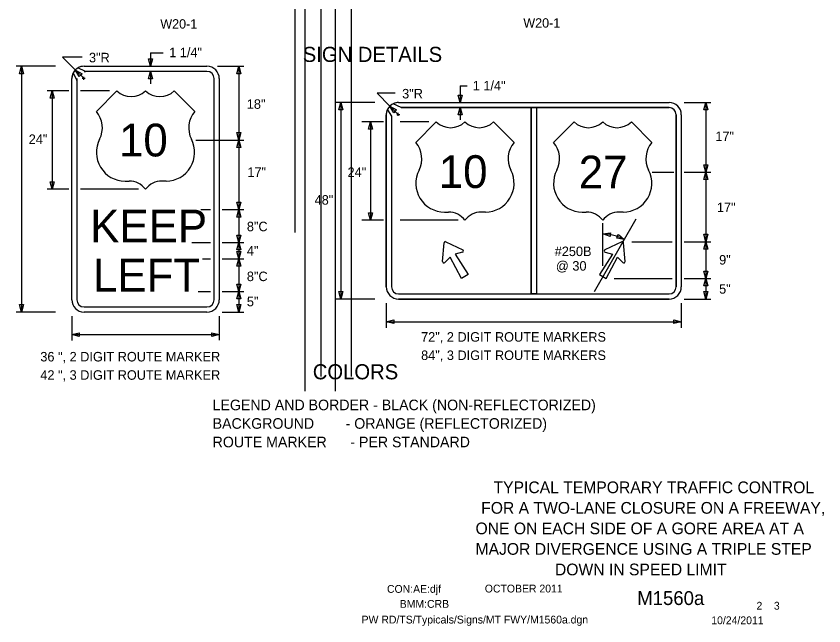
# Model space of a CAD drawing. Extents: x 16552 to 19508, y 5713 to 7079.
# Drawn here: x 17826 to 18466, y 5932 to 6416 of the extents above; entities that cross this region are included whole.
import ezdxf

# ---------------------------------------------------------------- set-up
doc = ezdxf.new("R2010")
doc.units = 0
for name, color, linetype in [('ALI_LEGAL_EX', 7, 'Continuous'), ('BORDER', 7, 'Continuous'), ('BORDER_SIGNAL_WO', 7, 'Continuous'), ('TRAFFIC_SIGNS_PR', 7, 'Continuous'), ('TYPICAL_EX', 7, 'Continuous'), ('TYPICAL_TEXT_DIMEN_PR', 7, 'Continuous')]:
    doc.layers.add(name, color=color, linetype=linetype)

msp = doc.modelspace()

# ---------------------------------------------------------------- linework, layer by layer
at = {"layer": 'ALI_LEGAL_EX'}
for p, q in [((18054.48, 7078.99), (18054.48, 6260.86)), ((18078.48, 7078.99), (18078.48, 6260.86)), ((18054.48, 6981.91), (18054.48, 6118)), ((18078.48, 6981.91), (18078.48, 6118)), ((18046.81, 6243.91), (18046.81, 6744.25)), ((18067.45, 6129.67), (18067.45, 6630.02)), ((18091.45, 6129.67), (18091.45, 6630.02))]:
    msp.add_line(p, q, dxfattribs=at)
at = {"layer": 'TRAFFIC_SIGNS_PR'}
for p, q in [((17879.4, 6375.92), (17976.9, 6375.92)), ((17871.82, 6372.3), (17870.82, 6370.79)), ((17870.84, 6370.72), (17873.72, 6364.68)), ((17880.61, 6371.86), (17874.51, 6374.6)), ((17976.9, 6371.86), (17879.4, 6371.86)), ((17869.65, 6190.67), (17869.65, 6366.17)), ((17873.72, 6366.17), (17873.72, 6190.67)), ((17982.59, 6190.67), (17982.59, 6366.17)), ((17986.65, 6366.17), (17986.65, 6190.67)), ((18130.88, 6343.17), (18124.65, 6346.19)), ((18128.92, 6347.22), (18343.42, 6347.22)), ((18128.92, 6347.22), (18343.42, 6347.22)), ((18130.86, 6343.16), (18234.14, 6343.16)), ((18343.42, 6343.16), (18130.86, 6343.16)), ((18234.14, 6343.16), (18234.14, 6195.28)), ((18238.21, 6343.16), (18238.21, 6195.28)), ((18238.21, 6343.16), (18343.42, 6343.16)), ((18119.17, 6337.47), (18119.17, 6200.97)), ((18119.17, 6200.97), (18119.17, 6337.47)), ((18120.09, 6341.48), (18123.23, 6336.44)), ((18349.11, 6337.47), (18349.11, 6291.72)), ((18349.11, 6200.97), (18349.11, 6337.47)), ((18353.17, 6337.47), (18353.17, 6200.97)), ((18353.17, 6337.47), (18353.17, 6200.97)), ((18123.24, 6336.42), (18123.24, 6200.97)), ((18123.24, 6336.42), (18123.24, 6200.97)), ((18349.11, 6291.72), (18349.11, 6200.97)), ((18163.78, 6221.08), (18164.93, 6235.8)), ((18166.44, 6236.67), (18179.75, 6230.31)), ((18305.91, 6236.67), (18292.59, 6230.31)), ((18308.57, 6221.08), (18307.42, 6235.8)), ((18128.92, 6195.28), (18343.42, 6195.28)), ((18128.92, 6191.22), (18343.42, 6191.22)), ((18343.42, 6191.22), (18128.92, 6191.22)), ((17879.4, 6184.98), (17976.9, 6184.98)), ((17976.9, 6180.92), (17879.4, 6180.92))]:
    msp.add_line(p, q, dxfattribs=at)
for points in [[(18130.86, 6343.16), (18130.85, 6343.16)], [(18123.23, 6336.44), (18123.24, 6336.42)], [(18179.59, 6228.34), (18173.87, 6226.76), (18184.09, 6210.59), (18178.69, 6207.47), (18169.79, 6224.41), (18165.57, 6220.24)], [(18292.76, 6228.34), (18298.48, 6226.76), (18288.26, 6210.59), (18293.66, 6207.47), (18302.56, 6224.41), (18306.78, 6220.24)]]:
    msp.add_lwpolyline(points, dxfattribs=at)
msp.add_lwpolyline([(18234.14, 6343.16), (18238.21, 6343.16), (18238.21, 6195.28), (18234.14, 6195.28)], close=True, dxfattribs=at)
for centre, radius, start, end in [((17879.4, 6366.17), 9.75, 90, 180), ((17878.82, 6368.34), 7.6, 85.58319, 124.53531), ((17976.9, 6366.17), 9.75, 0, 90), ((17876.69, 6366.76), 7.06, 145.86811, 184.82317), ((17880.01, 6376.28), 4.47, 262.2432, 277.7568), ((17976.9, 6366.17), 5.69, 0, 90), ((17868.26, 6365.43), 5.51, 352.24294, 7.75653), ((18128.92, 6337.47), 9.75, 90, 180), ((18128.92, 6337.47), 9.75, 90, 180), ((18128.25, 6340.65), 6.6, 84.11162, 123.06374), ((18129.86, 6350.34), 7.24, 277.81035, 278.05403), ((18343.42, 6337.47), 9.75, 0, 90), ((18343.42, 6337.47), 9.75, 0, 90), ((18343.42, 6337.47), 5.69, 0, 89.99421), ((18343.42, 6337.47), 5.69, 0, 90), ((18125.3, 6338.18), 6.17, 147.60925, 186.56283), ((18165.98, 6235.71), 1.06, 64.48226, 175.51774), ((18306.37, 6235.71), 1.06, 4.48226, 115.51774), ((18179.3, 6229.35), 1.06, 285.9885, 64.48226), ((18293.05, 6229.35), 1.06, 115.51774, 254.0115), ((18164.83, 6221), 1.06, 175.51775, 314.01151), ((18307.52, 6221), 1.06, 225.98849, 4.48225), ((18128.92, 6200.97), 9.75, 180, 270), ((18128.92, 6200.97), 9.75, 180, 270), ((18128.92, 6200.97), 5.69, 180, 270), ((18128.92, 6200.97), 5.69, 180, 270), ((18343.42, 6200.97), 9.75, 270, 0), ((18343.42, 6200.97), 5.69, 270, 0), ((18343.42, 6200.97), 9.75, 270, 0), ((18343.42, 6200.97), 5.69, 270, 0), ((17879.4, 6190.67), 9.75, 180, 270), ((17879.4, 6190.67), 5.69, 180, 270), ((17976.9, 6190.67), 5.69, 270, 0), ((17976.9, 6190.67), 9.75, 270, 0)]:
    msp.add_arc(centre, radius, start, end, dxfattribs=at)
at = {"layer": 'TYPICAL_EX'}
for p, q in [((17889.15, 6340.17), (17905.4, 6356.42)), ((17967.16, 6340.17), (17950.9, 6356.42)), ((18142.53, 6315.56), (18158.78, 6331.81)), ((18220.54, 6315.56), (18204.28, 6331.81)), ((18251.81, 6315.56), (18268.06, 6331.81)), ((18329.82, 6315.56), (18313.56, 6331.81)), ((17911.88, 6284.88), (17915.13, 6284.88)), ((17944.42, 6284.88), (17941.17, 6284.88)), ((18165.26, 6260.27), (18168.51, 6260.27)), ((18197.81, 6260.27), (18194.56, 6260.27)), ((18274.54, 6260.27), (18277.79, 6260.27)), ((18307.09, 6260.27), (18303.84, 6260.27))]:
    msp.add_line(p, q, dxfattribs=at)
for centre, radius, start, end in [((17916.78, 6368.26), 16.42, 226.14041, 313.85958), ((17939.53, 6368.26), 16.42, 226.14042, 313.85959), ((17873.75, 6327.16), 20.16, 333.09768, 40.19361), ((17982.55, 6327.16), 20.16, 139.80639, 206.90233), ((18170.16, 6343.65), 16.42, 226.14041, 313.85958), ((18192.91, 6343.65), 16.42, 226.14042, 313.85959), ((18279.44, 6343.65), 16.42, 226.14041, 313.85958), ((18302.19, 6343.65), 16.42, 226.14042, 313.85959), ((17911.92, 6307.6), 22.73, 152.6698, 269.90132), ((17944.38, 6307.6), 22.73, 270.09868, 27.3302), ((18127.13, 6302.55), 20.16, 333.09768, 40.19361), ((18235.94, 6302.55), 20.16, 139.80639, 206.90233), ((18236.41, 6302.55), 20.16, 333.09768, 40.19361), ((18345.21, 6302.55), 20.16, 139.80639, 206.90233), ((18165.3, 6282.99), 22.73, 152.6698, 269.90132), ((18197.77, 6282.99), 22.73, 270.09868, 27.3302), ((18274.58, 6282.99), 22.73, 152.6698, 269.90132), ((18307.05, 6282.99), 22.73, 270.09868, 27.3302), ((17915.17, 6268.6), 16.28, 37.1038, 90.13853), ((17941.13, 6268.6), 16.28, 89.86147, 142.8962), ((18168.55, 6243.99), 16.28, 37.1038, 90.13853), ((18194.52, 6243.99), 16.28, 89.86147, 142.8962), ((18277.83, 6243.99), 16.28, 37.1038, 90.13853), ((18303.8, 6243.99), 16.28, 89.86147, 142.8962)]:
    msp.add_arc(centre, radius, start, end, dxfattribs=at)
at = {"layer": 'TYPICAL_TEXT_DIMEN_PR'}
for p, q in [((17878.02, 6383.2), (17862.37, 6383.2)), ((17862.37, 6383.2), (17872.6, 6372.97)), ((17932.12, 6375.92), (17930.55, 6381.78)), ((17930.55, 6381.78), (17932.12, 6381.78)), ((17932.12, 6386.68), (17932.12, 6375.92)), ((17932.12, 6386.68), (17942.23, 6386.68)), ((17932.12, 6381.78), (17933.69, 6381.78)), ((17933.69, 6381.78), (17932.12, 6375.92)), ((17856.82, 6375.92), (17825.53, 6375.92)), ((17828.3, 6370.06), (17829.87, 6375.92)), ((17829.87, 6375.92), (17829.87, 6180.92)), ((17829.87, 6375.92), (17831.44, 6370.06)), ((17985.19, 6375.92), (18006.15, 6375.92)), ((18000.69, 6370.06), (18002.26, 6375.92)), ((18002.26, 6375.92), (18002.26, 6317.42)), ((18002.26, 6375.92), (18003.83, 6370.06)), ((17829.87, 6370.06), (17828.3, 6370.06)), ((17831.44, 6370.06), (17829.87, 6370.06)), ((17872.6, 6372.97), (17879.16, 6366.41)), ((17875.64, 6367.71), (17872.6, 6372.97)), ((17872.6, 6372.97), (17877.86, 6369.93)), ((17876.75, 6368.82), (17875.64, 6367.71)), ((17877.86, 6369.93), (17876.75, 6368.82)), ((17930.6, 6365.99), (17932.17, 6371.86)), ((17932.17, 6371.86), (17932.17, 6362.11)), ((17932.17, 6371.86), (17933.74, 6365.99)), ((18002.26, 6370.06), (18000.69, 6370.06)), ((18003.83, 6370.06), (18002.26, 6370.06)), ((17877.95, 6366.41), (17880.37, 6366.41)), ((17879.16, 6365.2), (17879.16, 6367.62)), ((17932.17, 6365.99), (17930.6, 6365.99)), ((17933.74, 6365.99), (17932.17, 6365.99)), ((17867.28, 6356.42), (17850.15, 6356.42)), ((17852.48, 6350.56), (17854.05, 6356.42)), ((17854.05, 6356.42), (17854.05, 6278.42)), ((17854.05, 6356.42), (17855.62, 6350.56)), ((17899.52, 6356.42), (17876.64, 6356.42)), ((18177.78, 6360.37), (18177.78, 6347.22)), ((18177.78, 6360.37), (18183.31, 6360.37)), ((17854.05, 6350.56), (17852.48, 6350.56)), ((17855.62, 6350.56), (17854.05, 6350.56)), ((18126.06, 6354.5), (18111.89, 6354.5)), ((18111.89, 6354.5), (18122.04, 6344.36)), ((18177.78, 6347.22), (18176.21, 6353.08)), ((18176.21, 6353.08), (18177.78, 6353.08)), ((18177.78, 6353.08), (18179.35, 6353.08)), ((18179.35, 6353.08), (18177.78, 6347.22)), ((18109.94, 6347.22), (18078.65, 6347.22)), ((18081.42, 6341.36), (18082.99, 6347.22)), ((18082.99, 6347.22), (18082.99, 6191.22)), ((18082.99, 6347.22), (18084.56, 6341.36)), ((18122.04, 6344.36), (18128.68, 6337.71)), ((18125.07, 6339.1), (18122.04, 6344.36)), ((18122.04, 6344.36), (18127.29, 6341.32)), ((18176.26, 6337.3), (18177.83, 6343.16)), ((18176.26, 6337.3), (18177.83, 6343.16)), ((18177.83, 6343.16), (18177.83, 6333.41)), ((18177.83, 6343.16), (18179.4, 6337.3)), ((18177.83, 6343.16), (18179.4, 6337.3)), ((18355.55, 6347.22), (18376.51, 6347.22)), ((18371.04, 6341.36), (18372.61, 6347.22)), ((18372.61, 6347.22), (18372.61, 6291.97)), ((18372.61, 6347.22), (18374.18, 6341.36)), ((18082.99, 6341.36), (18081.42, 6341.36)), ((18084.56, 6341.36), (18082.99, 6341.36)), ((18126.18, 6340.21), (18125.07, 6339.1)), ((18127.29, 6341.32), (18126.18, 6340.21)), ((18127.48, 6337.71), (18129.89, 6337.71)), ((18128.68, 6336.5), (18128.68, 6338.92)), ((18177.83, 6337.3), (18176.26, 6337.3)), ((18177.83, 6337.3), (18176.26, 6337.3)), ((18179.4, 6337.3), (18177.83, 6337.3)), ((18179.4, 6337.3), (18177.83, 6337.3)), ((18372.61, 6341.36), (18371.04, 6341.36)), ((18374.18, 6341.36), (18372.61, 6341.36)), ((18116.8, 6331.81), (18099.67, 6331.81)), ((18104.97, 6325.95), (18106.54, 6331.81)), ((18106.54, 6331.81), (18106.54, 6253.81)), ((18106.54, 6331.81), (18108.11, 6325.95)), ((18152.9, 6331.81), (18130.03, 6331.81)), ((18106.54, 6325.95), (18104.97, 6325.95)), ((18108.11, 6325.95), (18106.54, 6325.95)), ((17968.04, 6317.42), (18006.15, 6317.42)), ((18002.26, 6317.42), (18000.69, 6323.28)), ((18000.69, 6323.28), (18002.26, 6323.28)), ((18000.69, 6311.56), (18002.26, 6317.42)), ((18002.26, 6323.28), (18003.83, 6323.28)), ((18003.83, 6323.28), (18002.26, 6317.42)), ((18002.26, 6317.42), (18002.26, 6262.17)), ((18002.26, 6317.42), (18003.83, 6311.56)), ((18002.26, 6311.56), (18000.69, 6311.56)), ((18003.83, 6311.56), (18002.26, 6311.56)), ((18329.99, 6291.97), (18347.14, 6291.97)), ((18355.55, 6291.97), (18376.51, 6291.97)), ((18372.61, 6291.97), (18371.04, 6297.83)), ((18371.04, 6297.83), (18372.61, 6297.83)), ((18371.04, 6286.11), (18372.61, 6291.97)), ((18372.61, 6297.83), (18374.18, 6297.83)), ((18374.18, 6297.83), (18372.61, 6291.97)), ((18372.61, 6291.97), (18372.61, 6236.72)), ((18372.61, 6291.97), (18374.18, 6286.11)), ((18372.61, 6286.11), (18371.04, 6286.11)), ((18374.18, 6286.11), (18372.61, 6286.11)), ((17854.05, 6278.42), (17852.48, 6284.28)), ((17852.48, 6284.28), (17854.05, 6284.28)), ((17854.05, 6284.28), (17855.62, 6284.28)), ((17855.62, 6284.28), (17854.05, 6278.42)), ((17867.28, 6278.42), (17850.15, 6278.42)), ((17922.64, 6278.42), (17876.64, 6278.42)), ((18002.26, 6262.17), (18000.69, 6268.03)), ((18000.69, 6268.03), (18002.26, 6268.03)), ((18002.26, 6268.03), (18003.83, 6268.03)), ((18003.83, 6268.03), (18002.26, 6262.17)), ((17971.98, 6262.17), (17979.66, 6262.17)), ((17989.03, 6262.17), (18006.15, 6262.17)), ((18000.69, 6256.31), (18002.26, 6262.17)), ((18002.26, 6262.17), (18002.26, 6236.17)), ((18002.26, 6262.17), (18003.83, 6256.31)), ((18106.54, 6253.81), (18104.97, 6259.67)), ((18104.97, 6259.67), (18106.54, 6259.67)), ((18106.54, 6259.67), (18108.11, 6259.67)), ((18108.11, 6259.67), (18106.54, 6253.81)), ((18002.26, 6256.31), (18000.69, 6256.31)), ((18003.83, 6256.31), (18002.26, 6256.31)), ((18116.8, 6253.81), (18099.67, 6253.81)), ((18176.03, 6253.81), (18130.03, 6253.81)), ((18284.21, 6197.32), (18317.45, 6254.91)), ((18290.96, 6217.48), (18290.96, 6251.47)), ((18002.26, 6236.17), (18000.69, 6242.03)), ((18000.69, 6242.03), (18002.26, 6242.03)), ((18002.26, 6242.03), (18003.83, 6242.03)), ((18003.83, 6242.03), (18002.26, 6236.17)), ((18290.99, 6242.91), (18296.98, 6243.87)), ((18296.66, 6240.75), (18290.99, 6242.91)), ((18296.82, 6242.31), (18296.66, 6240.75)), ((18296.98, 6243.87), (18296.82, 6242.31)), ((18301.98, 6239.59), (18302.66, 6241.01)), ((18302.66, 6241.01), (18303.34, 6242.42)), ((18303.34, 6242.42), (18307.94, 6238.46)), ((18372.61, 6236.72), (18371.04, 6242.58)), ((18371.04, 6242.58), (18372.61, 6242.58)), ((18372.61, 6242.58), (18374.18, 6242.58)), ((18374.18, 6242.58), (18372.61, 6236.72)), ((17964.96, 6236.17), (17979.66, 6236.17)), ((17989.03, 6236.17), (18006.15, 6236.17)), ((18000.69, 6230.31), (18002.26, 6236.17)), ((18002.26, 6236.17), (18002.26, 6223.17)), ((18002.26, 6236.17), (18003.83, 6230.31)), ((18307.94, 6238.46), (18301.98, 6239.59)), ((18313.91, 6236.72), (18345.78, 6236.72)), ((18355.55, 6236.72), (18376.51, 6236.72)), ((18371.04, 6230.86), (18372.61, 6236.72)), ((18372.61, 6236.72), (18372.61, 6207.47)), ((18372.61, 6236.72), (18374.18, 6230.86)), ((18002.26, 6230.31), (18000.69, 6230.31)), ((18002.26, 6223.17), (18000.69, 6229.03)), ((18000.69, 6229.03), (18002.26, 6229.03)), ((18003.83, 6230.31), (18002.26, 6230.31)), ((18002.26, 6229.03), (18003.83, 6229.03)), ((18003.83, 6229.03), (18002.26, 6223.17)), ((18372.61, 6230.86), (18371.04, 6230.86)), ((18374.18, 6230.86), (18372.61, 6230.86)), ((17973.32, 6223.17), (17979.66, 6223.17)), ((17989.03, 6223.17), (18006.15, 6223.17)), ((18000.69, 6217.31), (18002.26, 6223.17)), ((18002.26, 6223.17), (18002.26, 6197.17)), ((18002.26, 6223.17), (18003.83, 6217.31)), ((18002.26, 6217.31), (18000.69, 6217.31)), ((18003.83, 6217.31), (18002.26, 6217.31)), ((18372.61, 6207.47), (18371.04, 6213.33)), ((18371.04, 6213.33), (18372.61, 6213.33)), ((18372.61, 6213.33), (18374.18, 6213.33)), ((18374.18, 6213.33), (18372.61, 6207.47)), ((18002.26, 6197.17), (18000.69, 6203.03)), ((18000.69, 6203.03), (18002.26, 6203.03)), ((18002.26, 6203.03), (18003.83, 6203.03)), ((18003.83, 6203.03), (18002.26, 6197.17)), ((18299.78, 6207.47), (18345.78, 6207.47)), ((18355.55, 6207.47), (18376.51, 6207.47)), ((18371.04, 6201.61), (18372.61, 6207.47)), ((18372.61, 6207.47), (18372.61, 6191.22)), ((18372.61, 6207.47), (18374.18, 6201.61)), ((17969.82, 6197.17), (17979.66, 6197.17)), ((17989.03, 6197.17), (18006.15, 6197.17)), ((18000.69, 6191.31), (18002.26, 6197.17)), ((18002.26, 6197.17), (18002.26, 6180.92)), ((18002.26, 6197.17), (18003.83, 6191.31)), ((18082.99, 6191.22), (18081.42, 6197.08)), ((18081.42, 6197.08), (18082.99, 6197.08)), ((18082.99, 6197.08), (18084.56, 6197.08)), ((18084.56, 6197.08), (18082.99, 6191.22)), ((18372.61, 6201.61), (18371.04, 6201.61)), ((18372.61, 6191.22), (18371.04, 6197.08)), ((18371.04, 6197.08), (18372.61, 6197.08)), ((18374.18, 6201.61), (18372.61, 6201.61)), ((18372.61, 6197.08), (18374.18, 6197.08)), ((18374.18, 6197.08), (18372.61, 6191.22)), ((18002.26, 6191.31), (18000.69, 6191.31)), ((18003.83, 6191.31), (18002.26, 6191.31)), ((18109.94, 6191.22), (18078.65, 6191.22)), ((18355.55, 6191.22), (18372.67, 6191.22)), ((18355.55, 6191.22), (18376.51, 6191.22)), ((18355.55, 6191.22), (18372.67, 6191.22)), ((17829.87, 6180.92), (17828.3, 6186.78)), ((17828.3, 6186.78), (17829.87, 6186.78)), ((17829.87, 6186.78), (17831.44, 6186.78)), ((17831.44, 6186.78), (17829.87, 6180.92)), ((18002.26, 6180.92), (18000.69, 6186.78)), ((18000.69, 6186.78), (18002.26, 6186.78)), ((18002.26, 6186.78), (18003.83, 6186.78)), ((18003.83, 6186.78), (18002.26, 6180.92)), ((18119.17, 6187.88), (18119.17, 6168.31)), ((18353.17, 6187.88), (18353.17, 6168.31)), ((17856.82, 6180.92), (17825.53, 6180.92)), ((17869.65, 6177.57), (17869.65, 6158.22)), ((17986.65, 6177.57), (17986.65, 6158.68)), ((17989.03, 6180.92), (18006.15, 6180.92)), ((18119.17, 6173.25), (18125.04, 6174.82)), ((18119.17, 6173.25), (18353.17, 6173.25)), ((18125.04, 6171.68), (18119.17, 6173.25)), ((18125.04, 6174.82), (18125.04, 6173.25)), ((18125.04, 6173.25), (18125.04, 6171.68)), ((18347.31, 6173.25), (18347.31, 6174.82)), ((18347.31, 6174.82), (18353.17, 6173.25)), ((18353.17, 6173.25), (18347.31, 6171.68)), ((18347.31, 6171.68), (18347.31, 6173.25)), ((17869.65, 6162.95), (17875.51, 6164.52)), ((17875.51, 6164.52), (17875.51, 6162.95)), ((17980.79, 6162.95), (17980.79, 6164.52)), ((17980.79, 6164.52), (17986.65, 6162.95)), ((17869.65, 6162.95), (17986.65, 6162.95)), ((17875.51, 6161.38), (17869.65, 6162.95)), ((17875.51, 6162.95), (17875.51, 6161.38)), ((17986.65, 6162.95), (17980.79, 6161.38)), ((17980.79, 6161.38), (17980.79, 6162.95))]:
    msp.add_line(p, q, dxfattribs=at)
msp.add_arc((18291.16, 6208.48), 34.39, 60.74521, 90.32117, dxfattribs=at)

# ---------------------------------------------------------------- texts
at = {"layer": 'BORDER'}
for s, p in [('TYPICAL TEMPORARY TRAFFIC CONTROL', (18204.21, 6037.14)), ('FOR A TWO-LANE CLOSURE ON A FREEWAY,', (18194.41, 6020.84)), ('ONE ON EACH SIDE OF A GORE AREA AT A ', (18189.92, 6004.54)), ('MAJOR DIVERGENCE USING A TRIPLE STEP ', (18189.92, 5988.24)), ('DOWN IN SPEED LIMIT', (18252.92, 5971.94))]:
    msp.add_text(s, height=9.3, dxfattribs=at).set_placement(p)
at = {"layer": 'BORDER_SIGNAL_WO'}
for s, height, p in [('CON:AE:djf  ', 6.2, (18119.69, 5958.06)), ('    OCTOBER 2011    ', 6.2, (18188.08, 5958.34)), ('    M1560a   ', 11, (18301.86, 5948.38)), ('BMM:CRB   ', 6.2, (18129.81, 5946.17)), (' 2    3 ', 6.2, (18410.45, 5944.7)), ('PW RD/TS/Typicals/Signs/MT FWY/M1560a.dgn      ', 6.2, (18099.55, 5933.71)), ('10/24/2011    ', 6.2, (18376.93, 5933.13))]:
    msp.add_text(s, height=height, dxfattribs=at).set_placement(p)
at = {"layer": 'TRAFFIC_SIGNS_PR'}
for s, height, p in [('W20-1', 7.44, (17939.87, 6405.86)), ('W20-1', 7.44, (18227.84, 6406.63)), ('10', 26, (17907.12, 6304.42)), ('10', 26, (18160.77, 6279.35)), ('27', 26, (18271.78, 6278.99)), ('KEEP', 26, (17884.26, 6236.17)), ('LEFT', 26, (17886.49, 6197.17))]:
    msp.add_text(s, height=height, dxfattribs=at).set_placement(p)
at = {"layer": 'TYPICAL_TEXT_DIMEN_PR'}
for s, height, p in [('1 1/4"', 7.55, (17946.93, 6383.17)), ('SIGN DETAILS', 12, (18052.88, 6379.39)), ('3"R', 7.55, (17883.29, 6379.08)), ('1 1/4"', 7.55, (18187.71, 6356.8)), ('3"R', 7.55, (18131.71, 6350.43)), ('18"', 7.55, (18008.49, 6342.19)), ('17"', 7.55, (18380.18, 6316.58)), ('24"', 7.55, (17835.5, 6314.3)), ('17"', 7.55, (18008.95, 6288.14)), ('24"', 7.55, (18088.4, 6288.14)), ('48"', 7.55, (18062.29, 6266.12)), ('17"', 7.55, (18381.39, 6260.22)), ('8"C', 7.55, (18008.53, 6245.03)), ('4" ', 7.55, (18008.53, 6225.77)), ('#250B', 7.55, (18252.73, 6225.31)), ('@ 30', 7.55, (18253.68, 6213.76)), ('9"', 7.55, (18383.17, 6218.57)), ('8"C', 7.55, (18008.53, 6205.44)), ('5"', 7.55, (18383.16, 6195.47)), ('5" ', 7.55, (18008.53, 6185.46)), ('72", 2 DIGIT ROUTE MARKERS', 7.55, (18146.75, 6157.39)), ('36 ", 2 DIGIT ROUTE MARKER', 7.55, (17844.7, 6141.69)), ('84", 3 DIGIT ROUTE MARKERS', 7.55, (18146.75, 6142.84)), ('COLORS', 12, (18060.82, 6127.5)), ('42 ", 3 DIGIT ROUTE MARKER', 7.55, (17844.7, 6127.14)), ('LEGEND AND BORDER - BLACK (NON-REFLECTORIZED)', 8.4, (17981.39, 6102.97)), ('BACKGROUND        - ORANGE (REFLECTORIZED)', 8.4, (17981.39, 6088.27)), ('ROUTE MARKER      - PER STANDARD', 8.4, (17981.39, 6073.57))]:
    msp.add_text(s, height=height, dxfattribs=at).set_placement(p)

doc.saveas('drawing.dxf')
